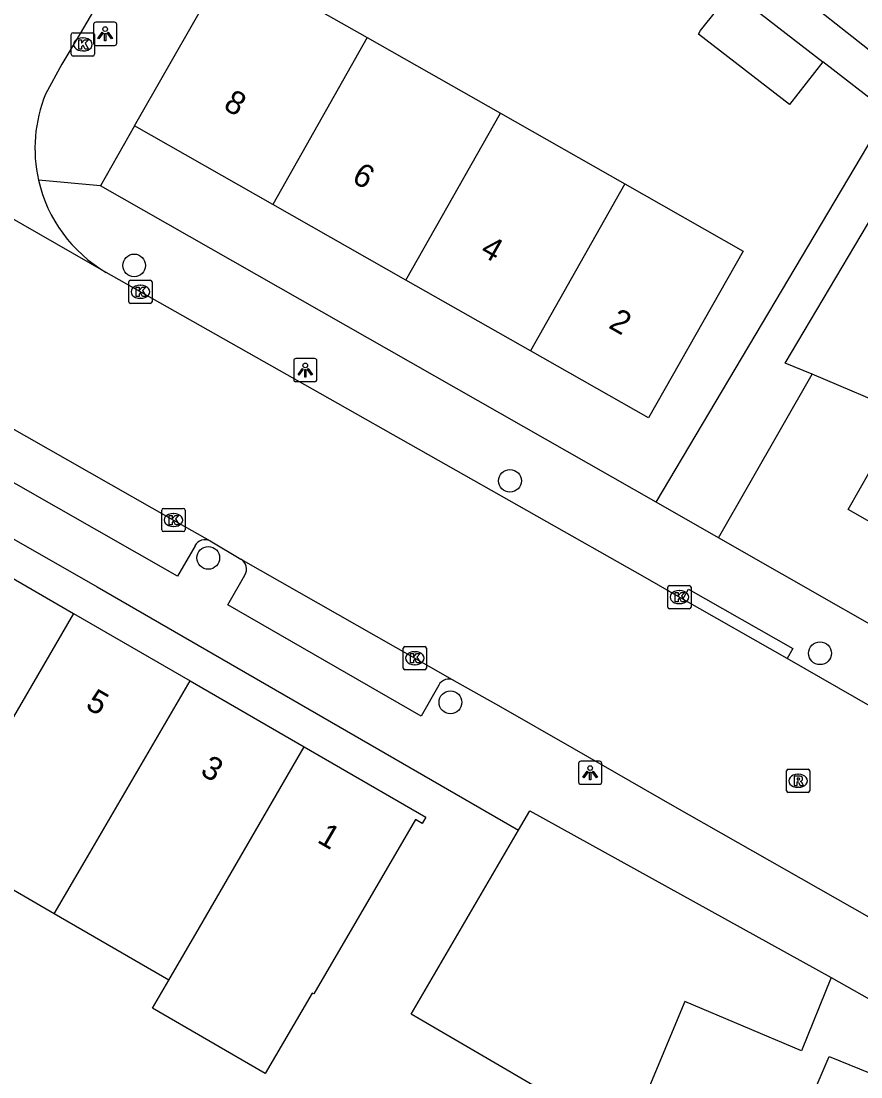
# Model space of a CAD drawing. Extents: x 160026 to 161302, y 384757 to 385701.
# Drawn here: x 160390.12 to 160426.25, y 385061.52 to 385106.98 of the extents above; entities that cross this region are included whole.
import ezdxf

# ---------------------------------------------------------------- set-up
doc = ezdxf.new("R2010")
doc.units = 0
for name, color, linetype in [('IMGEO_Boom', 7, 'Continuous'), ('IMGEO_Kolk', 7, 'Continuous'), ('IMGEO_Lichtpunt', 7, 'Continuous'), ('IMGEO_Pand', 7, 'Continuous'), ('IMGEO_Pand_nummerreeks', 7, 'Continuous'), ('IMGEO_Parkeervlak_open', 7, 'Continuous'), ('IMGEO_Rijbaan_lokaal_gesloten', 7, 'Continuous'), ('IMGEO_Rijbaan_lokaal_open', 7, 'Continuous'), ('IMGEO_Rioolput', 7, 'Continuous'), ('IMGEO_Voetpad_open', 7, 'Continuous')]:
    doc.layers.add(name, color=color, linetype=linetype)

msp = doc.modelspace()

# ---------------------------------------------------------------- linework, layer by layer
at = {"layer": 'IMGEO_Boom'}
for centre in [(160394.984, 385096.458), (160411.155, 385087.183), (160398.174, 385083.865), (160424.496, 385079.758), (160408.591, 385077.647)]:
    msp.add_circle(centre, 0.489, dxfattribs=at)
at = {"layer": 'IMGEO_Kolk'}
for p, q in [((160392.279, 385105.549), (160392.279, 385106.401)), ((160392.354, 385106.475), (160393.206, 385106.475)), ((160392.767, 385106.255), (160392.792, 385106.255)), ((160393.28, 385106.401), (160393.28, 385105.549)), ((160393.206, 385105.475), (160392.354, 385105.475)), ((160392.79, 385105.695), (160392.765, 385105.695)), ((160394.751, 385094.897), (160394.751, 385095.749)), ((160394.826, 385095.823), (160395.678, 385095.823)), ((160395.752, 385095.749), (160395.752, 385094.897)), ((160395.239, 385095.603), (160395.264, 385095.603)), ((160395.678, 385094.823), (160394.826, 385094.823)), ((160395.262, 385095.043), (160395.237, 385095.043)), ((160396.172, 385085.07), (160396.172, 385085.922)), ((160396.247, 385085.996), (160397.099, 385085.996)), ((160396.66, 385085.776), (160396.685, 385085.776)), ((160397.173, 385085.922), (160397.173, 385085.07)), ((160397.099, 385084.996), (160396.247, 385084.996)), ((160396.683, 385085.216), (160396.658, 385085.216)), ((160417.945, 385081.751), (160417.945, 385082.603)), ((160418.02, 385082.677), (160418.872, 385082.677)), ((160418.946, 385082.603), (160418.946, 385081.751)), ((160418.433, 385082.457), (160418.458, 385082.457)), ((160418.872, 385081.677), (160418.02, 385081.677)), ((160418.456, 385081.897), (160418.431, 385081.897)), ((160406.559, 385079.121), (160406.559, 385079.973)), ((160406.634, 385080.047), (160407.486, 385080.047)), ((160407.047, 385079.827), (160407.072, 385079.827)), ((160407.56, 385079.973), (160407.56, 385079.121)), ((160407.486, 385079.047), (160406.634, 385079.047)), ((160407.07, 385079.267), (160407.045, 385079.267))]:
    msp.add_line(p, q, dxfattribs=at)
for points in [[(160392.279, 385105.549), (160392.279, 385106.401)], [(160392.354, 385106.475), (160393.206, 385106.475)], [(160393.28, 385106.401), (160393.28, 385105.549)], [(160392.6, 385106.175), (160392.723, 385106.175), (160392.723, 385106.024), (160392.853, 385106.175), (160393.017, 385106.175), (160392.871, 385106.024), (160393.024, 385105.775), (160392.872, 385105.775), (160392.787, 385105.939), (160392.723, 385105.872), (160392.723, 385105.775), (160392.6, 385105.775), (160392.6, 385106.175)], [(160393.206, 385105.475), (160392.354, 385105.475)], [(160394.751, 385094.897), (160394.751, 385095.749)], [(160394.826, 385095.823), (160395.678, 385095.823)], [(160395.752, 385095.749), (160395.752, 385094.897)], [(160395.072, 385095.523), (160395.195, 385095.523), (160395.195, 385095.372), (160395.325, 385095.523), (160395.489, 385095.523), (160395.343, 385095.372), (160395.496, 385095.123), (160395.344, 385095.123), (160395.259, 385095.287), (160395.195, 385095.22), (160395.195, 385095.123), (160395.072, 385095.123), (160395.072, 385095.523)], [(160395.678, 385094.823), (160394.826, 385094.823)], [(160396.172, 385085.07), (160396.172, 385085.922)], [(160396.247, 385085.996), (160397.099, 385085.996)], [(160397.173, 385085.922), (160397.173, 385085.07)], [(160396.493, 385085.696), (160396.616, 385085.696), (160396.616, 385085.545), (160396.746, 385085.696), (160396.91, 385085.696), (160396.764, 385085.545), (160396.917, 385085.296), (160396.765, 385085.296), (160396.68, 385085.46), (160396.616, 385085.393), (160396.616, 385085.296), (160396.493, 385085.296), (160396.493, 385085.696)], [(160397.099, 385084.996), (160396.247, 385084.996)], [(160417.945, 385081.751), (160417.945, 385082.603)], [(160418.02, 385082.677), (160418.872, 385082.677)], [(160418.946, 385082.603), (160418.946, 385081.751)], [(160418.266, 385082.377), (160418.389, 385082.377), (160418.389, 385082.226), (160418.519, 385082.377), (160418.683, 385082.377), (160418.537, 385082.226), (160418.69, 385081.977), (160418.538, 385081.977), (160418.453, 385082.141), (160418.389, 385082.074), (160418.389, 385081.977), (160418.266, 385081.977), (160418.266, 385082.377)], [(160418.872, 385081.677), (160418.02, 385081.677)], [(160406.559, 385079.121), (160406.559, 385079.973)], [(160406.634, 385080.047), (160407.486, 385080.047)], [(160407.56, 385079.973), (160407.56, 385079.121)], [(160406.88, 385079.747), (160407.003, 385079.747), (160407.003, 385079.596), (160407.133, 385079.747), (160407.297, 385079.747), (160407.151, 385079.596), (160407.304, 385079.347), (160407.152, 385079.347), (160407.067, 385079.511), (160407.003, 385079.444), (160407.003, 385079.347), (160406.88, 385079.347), (160406.88, 385079.747)], [(160407.486, 385079.047), (160406.634, 385079.047)]]:
    msp.add_lwpolyline(points, dxfattribs=at)
for centre, start, end in [((160392.356, 385106.399), 91.552, 178.448), ((160392.356, 385106.399), 91.552, 178.448), ((160393.204, 385106.399), 1.552, 88.448), ((160393.204, 385106.399), 1.552, 88.448), ((160392.356, 385105.551), 181.552, 268.448), ((160392.356, 385105.551), 181.552, 268.448), ((160393.204, 385105.551), 271.552, 358.448), ((160393.204, 385105.551), 271.552, 358.448), ((160394.828, 385095.747), 91.552, 178.448), ((160394.828, 385095.747), 91.552, 178.448), ((160395.676, 385095.747), 1.552, 88.448), ((160395.676, 385095.747), 1.552, 88.448), ((160394.828, 385094.899), 181.552, 268.448), ((160394.828, 385094.899), 181.552, 268.448), ((160395.676, 385094.899), 271.552, 358.448), ((160395.676, 385094.899), 271.552, 358.448), ((160396.249, 385085.92), 91.552, 178.448), ((160396.249, 385085.92), 91.552, 178.448), ((160397.097, 385085.92), 1.552, 88.448), ((160397.097, 385085.92), 1.552, 88.448), ((160396.249, 385085.072), 181.552, 268.448), ((160396.249, 385085.072), 181.552, 268.448), ((160397.097, 385085.072), 271.552, 358.448), ((160397.097, 385085.072), 271.552, 358.448), ((160418.022, 385082.601), 91.552, 178.448), ((160418.022, 385082.601), 91.552, 178.448), ((160418.87, 385082.601), 1.552, 88.448), ((160418.87, 385082.601), 1.552, 88.448), ((160418.022, 385081.753), 181.552, 268.448), ((160418.022, 385081.753), 181.552, 268.448), ((160418.87, 385081.753), 271.552, 358.448), ((160418.87, 385081.753), 271.552, 358.448), ((160406.636, 385079.971), 91.552, 178.448), ((160406.636, 385079.971), 91.552, 178.448), ((160407.484, 385079.971), 1.552, 88.448), ((160407.484, 385079.971), 1.552, 88.448), ((160406.636, 385079.123), 181.552, 268.448), ((160406.636, 385079.123), 181.552, 268.448), ((160407.484, 385079.123), 271.552, 358.448), ((160407.484, 385079.123), 271.552, 358.448)]:
    msp.add_arc(centre, 0.0765, start, end, dxfattribs=at)
for centre, major_axis, ratio, start_param, end_param in [((160392.766, 385105.975), (-0.387, 0.002), 0.722429, 4.712389, 7.853982), ((160392.791, 385105.975), (-0.39, 0.002), 0.717154, 1.570796, 4.712389), ((160395.238, 385095.323), (-0.387, 0.002), 0.722429, 4.712389, 7.853982), ((160395.263, 385095.323), (-0.39, 0.002), 0.717154, 1.570796, 4.712389), ((160396.659, 385085.496), (-0.387, 0.002), 0.722429, 4.712389, 7.853982), ((160396.684, 385085.496), (-0.39, 0.002), 0.717154, 1.570796, 4.712389), ((160418.432, 385082.177), (-0.387, 0.002), 0.722429, 4.712389, 7.853982), ((160418.457, 385082.177), (-0.39, 0.002), 0.717154, 1.570796, 4.712389), ((160407.046, 385079.547), (-0.387, 0.002), 0.722429, 4.712389, 7.853982), ((160407.071, 385079.547), (-0.39, 0.002), 0.717154, 1.570796, 4.712389)]:
    msp.add_ellipse(centre, major_axis=major_axis, ratio=ratio, start_param=start_param, end_param=end_param, dxfattribs=at)
at = {"layer": 'IMGEO_Lichtpunt'}
for p, q in [((160393.236, 385106.835), (160393.236, 385106.028)), ((160393.236, 385106.835), (160393.236, 385106.028)), ((160394.138, 385106.93), (160393.33, 385106.93)), ((160394.138, 385106.93), (160393.33, 385106.93)), ((160394.232, 385106.028), (160394.232, 385106.835)), ((160394.232, 385106.028), (160394.232, 385106.835)), ((160393.33, 385105.934), (160394.138, 385105.934)), ((160393.33, 385105.934), (160394.138, 385105.934)), ((160401.849, 385092.355), (160401.849, 385091.548)), ((160401.849, 385092.355), (160401.849, 385091.548)), ((160402.751, 385092.45), (160401.943, 385092.45)), ((160402.751, 385092.45), (160401.943, 385092.45)), ((160402.845, 385091.548), (160402.845, 385092.355)), ((160402.845, 385091.548), (160402.845, 385092.355)), ((160401.943, 385091.454), (160402.751, 385091.454)), ((160401.943, 385091.454), (160402.751, 385091.454)), ((160414.107, 385075.018), (160414.107, 385074.211)), ((160414.107, 385075.018), (160414.107, 385074.211)), ((160415.009, 385075.113), (160414.201, 385075.113)), ((160415.009, 385075.113), (160414.201, 385075.113)), ((160415.103, 385074.211), (160415.103, 385075.018)), ((160415.103, 385074.211), (160415.103, 385075.018)), ((160414.201, 385074.117), (160415.009, 385074.117)), ((160414.201, 385074.117), (160415.009, 385074.117))]:
    msp.add_line(p, q, dxfattribs=at)
for points in [[(160393.61, 385106.499), (160393.649, 385106.471), (160393.461, 385106.209), (160393.423, 385106.236), (160393.61, 385106.499)], [(160393.712, 385106.451), (160393.759, 385106.451), (160393.759, 385106.129), (160393.712, 385106.129), (160393.712, 385106.451)], [(160393.822, 385106.471), (160393.86, 385106.498), (160394.047, 385106.236), (160394.008, 385106.208), (160393.822, 385106.471)], [(160402.223, 385092.019), (160402.262, 385091.991), (160402.074, 385091.729), (160402.036, 385091.756), (160402.223, 385092.019)], [(160402.325, 385091.971), (160402.372, 385091.971), (160402.372, 385091.649), (160402.325, 385091.649), (160402.325, 385091.971)], [(160402.435, 385091.991), (160402.473, 385092.018), (160402.66, 385091.756), (160402.621, 385091.728), (160402.435, 385091.991)], [(160414.481, 385074.682), (160414.52, 385074.654), (160414.332, 385074.392), (160414.294, 385074.419), (160414.481, 385074.682)], [(160414.583, 385074.634), (160414.63, 385074.634), (160414.63, 385074.312), (160414.583, 385074.312), (160414.583, 385074.634)], [(160414.693, 385074.654), (160414.731, 385074.681), (160414.918, 385074.419), (160414.879, 385074.391), (160414.693, 385074.654)]]:
    msp.add_lwpolyline(points, dxfattribs=at)
for centre in [(160393.735, 385106.633), (160402.348, 385092.153), (160414.606, 385074.816)]:
    msp.add_circle(centre, 0.0994, dxfattribs=at)
for centre, start, end in [((160393.33, 385106.835), 90, 180), ((160393.33, 385106.835), 90, 180), ((160394.138, 385106.835), 0, 90), ((160394.138, 385106.835), 0, 90), ((160393.33, 385106.028), 180, 270), ((160393.33, 385106.028), 180, 270), ((160394.138, 385106.028), 270, 0), ((160394.138, 385106.028), 270, 360), ((160401.943, 385092.355), 90, 180), ((160401.943, 385092.355), 90, 180), ((160402.751, 385092.355), 0, 90), ((160402.751, 385092.355), 0, 90), ((160401.943, 385091.548), 180, 270), ((160401.943, 385091.548), 180, 270), ((160402.751, 385091.548), 270, 0), ((160402.751, 385091.548), 270, 360), ((160414.201, 385075.018), 90, 180), ((160414.201, 385075.018), 90, 180), ((160415.009, 385075.018), 0, 90), ((160415.009, 385075.018), 0, 90), ((160414.201, 385074.211), 180, 270), ((160414.201, 385074.211), 180, 270), ((160415.009, 385074.211), 270, 0), ((160415.009, 385074.211), 270, 360)]:
    msp.add_arc(centre, 0.0946, start, end, dxfattribs=at)
at = {"layer": 'IMGEO_Pand'}
for points in [[(160395.003, 385102.463), (160399.08, 385109.636)], [(160399.08, 385109.636), (160405.009, 385106.266)], [(160424.617, 385105.23), (160423.181, 385103.383), (160419.269, 385106.422), (160419.357, 385106.577), (160420.704, 385108.271)], [(160420.704, 385108.271), (160424.617, 385105.23)], [(160405.009, 385106.266), (160400.946, 385099.085)], [(160405.009, 385106.266), (160410.741, 385103.008)], [(160406.678, 385095.827), (160410.741, 385103.008)], [(160410.741, 385103.008), (160416.095, 385099.965)], [(160400.946, 385099.085), (160395.003, 385102.463)], [(160416.095, 385099.965), (160421.19, 385097.069), (160417.112, 385089.896), (160412.033, 385092.783)], [(160416.095, 385099.965), (160412.033, 385092.783)], [(160406.678, 385095.827), (160400.946, 385099.085)], [(160412.033, 385092.783), (160406.678, 385095.827)], [(160420.134, 385084.726), (160424.153, 385091.772)], [(160430.992, 385078.531), (160432.889, 385081.856), (160425.703, 385085.956), (160428.077, 385090.118), (160424.153, 385091.772)], [(160387.369, 385084.371), (160392.379, 385081.472)], [(160430.992, 385078.531), (160420.134, 385084.726)], [(160392.379, 385081.472), (160387.873, 385073.731), (160386.745, 385071.786)], [(160392.379, 385081.472), (160397.389, 385078.574)], [(160391.544, 385068.543), (160392.871, 385070.82), (160397.389, 385078.574)], [(160397.389, 385078.574), (160402.304, 385075.731)], [(160402.304, 385075.731), (160407.53, 385072.707), (160407.37, 385072.431), (160407.085, 385072.598), (160402.712, 385065.089), (160402.639, 385065.131), (160400.617, 385061.659), (160395.774, 385064.479), (160396.473, 385065.684)], [(160396.473, 385065.684), (160397.791, 385067.955), (160402.304, 385075.731)], [(160391.544, 385068.543), (160386.545, 385071.442), (160386.745, 385071.786)], [(160396.473, 385065.684), (160391.544, 385068.543)], [(160416.228, 385058.883), (160418.844, 385057.768), (160418.33, 385056.562), (160421.77, 385055.094), (160424.883, 385062.397), (160437.345, 385057.328), (160437.192, 385056.925), (160437.809, 385056.671), (160436.374, 385053.189), (160435.815, 385053.42), (160433.49, 385047.781)]]:
    msp.add_lwpolyline(points, dxfattribs=at)
at = {"layer": 'IMGEO_Parkeervlak_open'}
for points in [[(160415.579, 385059.16), (160406.899, 385064.215), (160411.517, 385072.145)], [(160424.98, 385065.798), (160423.699, 385062.643), (160418.68, 385064.766), (160416.228, 385058.883)]]:
    msp.add_lwpolyline(points, dxfattribs=at)
at = {"layer": 'IMGEO_Rijbaan_lokaal_gesloten'}
for points in [[(160393.778, 385096.16), (160379.385, 385104.426)], [(160375.168, 385097.761), (160378.639, 385095.752), (160386.711, 385091.158), (160396.67, 385085.497), (160398.258, 385084.596)], [(160418.598, 385082.089), (160416.968, 385083.016), (160402.988, 385090.942), (160394.009, 385096.026), (160393.778, 385096.16)], [(160398.258, 385084.596), (160399.574, 385083.817)], [(160399.574, 385083.817), (160407.061, 385079.548), (160408.745, 385078.592)], [(160423.083, 385079.537), (160418.598, 385082.089)], [(160441.257, 385069.142), (160438.8, 385070.504), (160435.644, 385072.318), (160423.083, 385079.537)], [(160408.745, 385078.592), (160410.666, 385077.515), (160413.918, 385075.639), (160418.139, 385073.218), (160424.416, 385069.645), (160428.901, 385067.092), (160437.316, 385062.291)]]:
    msp.add_lwpolyline(points, dxfattribs=at)
at = {"layer": 'IMGEO_Rijbaan_lokaal_open'}
msp.add_lwpolyline([(160448.926, 385179.255), (160441.301, 385169.642), (160436.8, 385163.928), (160428.03, 385152.903), (160419.879, 385142.636), (160410.04, 385130.111), (160402.173, 385120.293), (160397.425, 385114.032), (160393.624, 385108.1), (160392.655, 385106.45), (160391.867, 385105.123), (160391.174, 385103.832)], dxfattribs=at)
for centre, radius, start, end in [((160396.889, 385101.496), 6.174, 157.7714, 192.8165), ((160396.9, 385101.499), 6.185, 192.8184, 239.6867)]:
    msp.add_arc(centre, radius, start, end, dxfattribs=at)
at = {"layer": 'IMGEO_Rioolput'}
for p, q in [((160423.053, 385073.842), (160423.053, 385074.694)), ((160423.128, 385074.768), (160423.98, 385074.768)), ((160423.541, 385074.548), (160423.566, 385074.548)), ((160424.054, 385074.694), (160424.054, 385073.842)), ((160423.564, 385073.988), (160423.539, 385073.988)), ((160423.98, 385073.768), (160423.128, 385073.768))]:
    msp.add_line(p, q, dxfattribs=at)
for points in [[(160423.053, 385073.842), (160423.053, 385074.694)], [(160423.128, 385074.768), (160423.98, 385074.768)], [(160423.642, 385074.466), (160423.39, 385074.468), (160423.39, 385074.068)], [(160423.568, 385074.387), (160423.514, 385074.387), (160423.514, 385074.306)], [(160424.054, 385074.694), (160424.054, 385073.842)], [(160423.39, 385074.068), (160423.514, 385074.068), (160423.514, 385074.23), (160423.525, 385074.23)], [(160423.514, 385074.306), (160423.566, 385074.306)], [(160423.572, 385074.201), (160423.643, 385074.068), (160423.783, 385074.068), (160423.718, 385074.194)], [(160423.98, 385073.768), (160423.128, 385073.768)]]:
    msp.add_lwpolyline(points, dxfattribs=at)
for centre, radius, start, end in [((160423.13, 385074.692), 0.0765, 91.552, 178.448), ((160423.13, 385074.692), 0.0765, 91.552, 178.448), ((160423.574, 385074.291), 0.0964, 77.0061, 93.1865), ((160423.588, 385074.348), 0.0378, 276.6634, 79.6772), ((160423.641, 385074.356), 0.109, 350.3612, 89.416), ((160423.978, 385074.692), 0.0765, 1.552, 88.448), ((160423.978, 385074.692), 0.0765, 1.552, 88.448), ((160423.524, 385074.177), 0.0533, 26.0293, 88.6989), ((160423.55, 385074.495), 0.19, 274.7715, 282.9687), ((160423.639, 385074.356), 0.112, 277.5842, 350.9817), ((160423.623, 385074.141), 0.108, 29.5134, 73.7905), ((160423.13, 385073.844), 0.0765, 181.552, 268.448), ((160423.13, 385073.844), 0.0765, 181.552, 268.448), ((160423.978, 385073.844), 0.0765, 271.552, 358.448), ((160423.978, 385073.844), 0.0765, 271.552, 358.448)]:
    msp.add_arc(centre, radius, start, end, dxfattribs=at)
for centre, major_axis, ratio, start_param, end_param in [((160423.54, 385074.268), (-0.387, 0.002), 0.722429, 4.712389, 7.853982), ((160423.565, 385074.268), (-0.39, 0.002), 0.717154, 1.570796, 4.712389)]:
    msp.add_ellipse(centre, major_axis=major_axis, ratio=ratio, start_param=start_param, end_param=end_param, dxfattribs=at)
at = {"layer": 'IMGEO_Voetpad_open'}
for points in [[(160429.309, 385105.761), (160428.436, 385104.286), (160414.516, 385115.27)], [(160424.153, 385091.772), (160423.001, 385092.257), (160431.712, 385106.94)], [(160417.444, 385086.258), (160427.408, 385103.06), (160424.617, 385105.23)], [(160395.003, 385102.463), (160393.531, 385099.882)], [(160360.355, 385101.627), (160373.936, 385093.737), (160393.395, 385082.624), (160411.517, 385072.145)], [(160393.531, 385099.882), (160390.869, 385100.127)], [(160417.444, 385086.258), (160393.531, 385099.882)], [(160397.602, 385084.387), (160396.85, 385083.083), (160386.424, 385089.022), (160387.028, 385090.046)], [(160420.134, 385084.726), (160417.444, 385086.258)], [(160408.091, 385078.388), (160407.337, 385077.058), (160399.015, 385081.845), (160399.751, 385083.128)], [(160418.598, 385082.089), (160418.843, 385082.52), (160423.329, 385079.97), (160423.083, 385079.537)], [(160411.517, 385072.145), (160412.003, 385072.979), (160424.98, 385065.798)], [(160424.98, 385065.798), (160438.609, 385058.093)]]:
    msp.add_lwpolyline(points, dxfattribs=at)
for centre, radius, start, end in [((160398.037, 385084.156), 0.493, 63.3374, 152.0062), ((160399.32, 385083.385), 0.501, 329.2043, 59.6105), ((160408.52, 385078.164), 0.483, 62.1948, 152.4534)]:
    msp.add_arc(centre, radius, start, end, dxfattribs=at)

# ---------------------------------------------------------------- texts
at = {"layer": 'IMGEO_Pand_nummerreeks'}
for s, rotation, p in [('8', 330.3856, (160398.776, 385103.217)), ('6', 330.3856, (160404.3, 385100.078)), ('4', 330.3856, (160409.827, 385096.936)), ('2', 330.3856, (160415.352, 385093.795)), ('5', 329.9426, (160392.846, 385077.415)), ('3', 329.9426, (160397.781, 385074.559)), ('1', 329.9426, (160402.814, 385071.646))]:
    msp.add_text(s, height=1, rotation=rotation, dxfattribs=at).set_placement(p)

doc.saveas('drawing.dxf')
